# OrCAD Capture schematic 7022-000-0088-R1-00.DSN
size A3; title: TFA8200 Mono Translation Board; rev: 1.00; company: Voice & Audio Solutions; note: 7022-000-0088; note: Ernst van Ingen
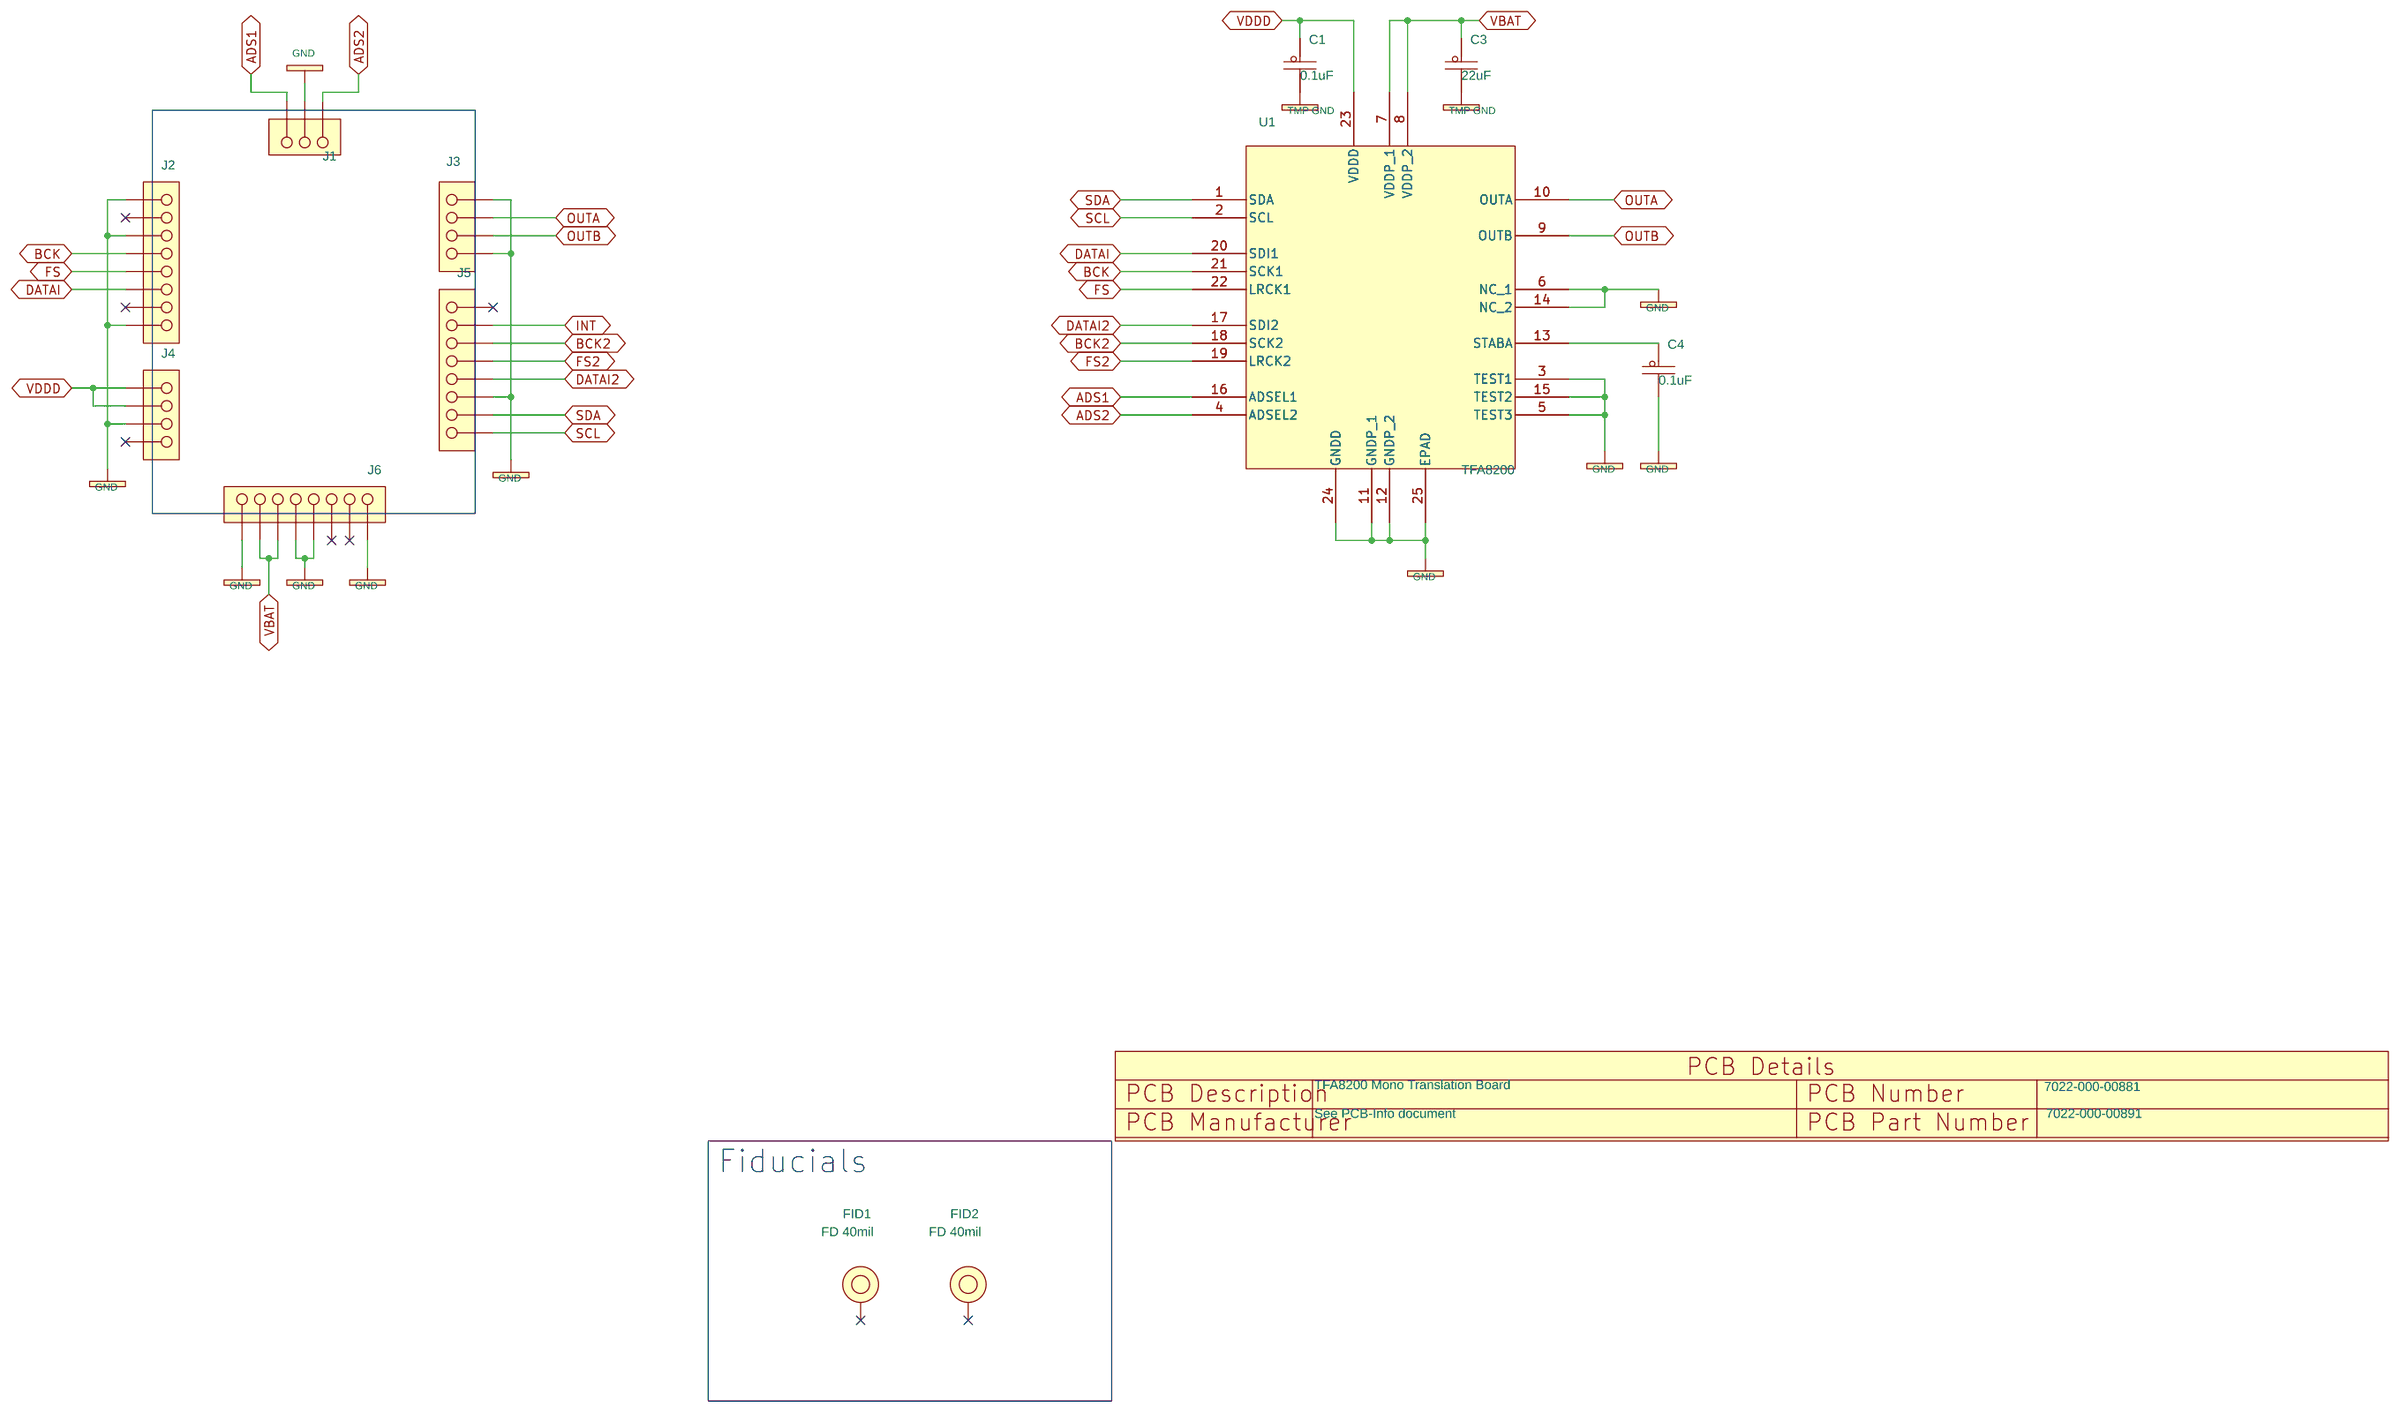
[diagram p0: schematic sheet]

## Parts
0001  PCB-NUMBER  [MEC_PCB-NUMBER]
C1  0.1uF  [CC0201]
C3  22uF  [CC0603_OV]
C4  0.1uF  [CC0201]
FID1  FD 40mil  [FID_40MIL_SM080]
FID2  FD 40mil  [FID_40MIL_SM080]
J1  HDR_1X3  [con_1x3_1p27_th]
J2  HDR_1X8  [con_1x8_1p27_th]
J3  HDR_1X4  [con_1x4_1p27_th]
J4  HDR_1X4  [con_1x4_1p27_th]
J5  HDR_1X8  [con_1x8_1p27_th]
J6  HDR_1X8  [con_1x8_1p27_th]
U1  TFA8200  [qfn24_0p5_4x4_ep]

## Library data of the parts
0001 = PCB-NUMBER-2: TFA8200 Mono Translation Board; Department: TCN; Department Status: Preferred; HEIGHT: 0.0; Manufacturer: See PCB-Info document; Manufacturer Part Number: See PCB-Info document; PCB-NUMBER: 7022-000-00881; Part Number: 7022-000-00891
C1 C4 = CAP_NP: CAP CER 0.1uF 16V 10% X5R 0201; AGILE_PN: 150-80059; CAD_APPROVED: Yes; FPLIST: CC0201,CC0201_HD,0201_CC; HEIGHT: 0.33MM; MFG_NAME01: MURATA; MFG_PN01: GRM033R61C104KE14D; ROHS: Yes; Temp_Range: -55 to +85°C; Tolerance: 10%; VOLTAGE: 16V
C3 = CAP_NP: CAP CER 22uF 10V 20% X5R 0603; AGILE_PN: 150-79530; CAD_APPROVED: Yes; FPLIST: CC0603_OV,CC0603,0603_CC; HEIGHT: 1MM; MFG_NAME01: TDK; MFG_PN01: C1608X5R1A226M080AC; ROHS: Yes; Tolerance: 20%; VOLTAGE: 10V
FID1 FID2 = FID-040: FIDUCIAL PLATED 40mil PAD 80mil SOLDERMASK SMD, NO PART TO ORDER; AGILE_PN: 510-77655; CAD_APPROVED: Yes; HEIGHT: 0.1MM; MFG_NAME01: NO PART TO ORDER; MFG_PN01: Local fiducial; ROHS: Yes
J1 = CONN_HDR_3X1: HDR 1X3 TH 50MIL SP 165H AU 90L; AGILE_PN: 210-81786; CAD_APPROVED: Yes; HEIGHT: 4.2 mm; MFG_NAME01: HARWIN INC; MFG_PN01: M50-3530342; ROHS: Yes; Temp_Range: -40 to +105C
J2 J5 J6 = CONN_HDR_8X1: HDR 1X8 TH 50MIL SP 165H AU 90L; AGILE_PN: 210-81784; CAD_APPROVED: Yes; HEIGHT: 4.2 mm; MFG_NAME01: HARWIN INC; MFG_PN01: M50-3530842; ROHS: Yes; Temp_Range: -40 to +105C
J3 J4 = CONN_HDR_4X1: HDR 1X4 TH 50MIL SP 165H AU 90L; AGILE_PN: 210-81785; CAD_APPROVED: Yes; HEIGHT: 4.2 mm; MFG_NAME01: HARWIN INC; MFG_PN01: M50-3530442; ROHS: Yes; Temp_Range: -40 to +105C
U1 = TFA8200_QFN_24P: IC AUD AMP CLASS D IOT 2.5-5.5V HVQFN24; AGILE_PN: TMP-WF-35236; CAD_APPROVED: Yes; HEIGHT: 1MM; MFG_NAME01: NXP SEMICONDUCTORS; MFG_PN01: TFA8200HN; PRE_APN: 312-82189; ROHS: Yes

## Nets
GND: C1.2 C3.2 C4.2 J1.2 J2.1 J2.3 J2.8 J3.1 J3.4 J4.3 J5.6 J6.1 J6.4 J6.5 J6.8 U1.3(TEST1) U1.5(TEST3) U1.6(NC_1) U1.11(GNDP_1) U1.12(GNDP_2) U1.14(NC_2) U1.15(TEST2) U1.24(GNDD) U1.25(EPAD)
VBAT: C3.1 J6.2 J6.3 U1.7(VDDP_1) U1.8(VDDP_2)
VDDD: C1.1 J4.1 J4.2 U1.23(VDDD)
ADS1: J1.1 U1.16(ADSEL1)
ADS2: J1.3 U1.4(ADSEL2)
BCK: J2.4 U1.21(SCK1)
BCK2: J5.3 U1.18(SCK2)
DATAI: J2.6 U1.20(SDI1)
DATAI2: J5.5 U1.17(SDI2)
FS: J2.5 U1.22(LRCK1)
FS2: J5.4 U1.19(LRCK2)
INT: J5.2
OUTA: J3.2 U1.10(OUTA)
OUTB: J3.3 U1.9(OUTB)
SCL: J5.8 U1.2(SCL)
SDA: J5.7 U1.1(SDA)
N14931714: C4.1 U1.13(STABA)

Not connected (* = marked no-connect by the designer): 0001 1; FID1 1(NC)*; FID2 1(NC)*; J2 2* 7*; J4 4*; J5 1*; J6 6* 7*

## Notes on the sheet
- Fiducials
